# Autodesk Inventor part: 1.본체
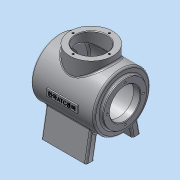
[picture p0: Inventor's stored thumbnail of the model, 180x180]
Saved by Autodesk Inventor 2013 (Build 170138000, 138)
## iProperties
Created: 2015-01
Part Number: 1.본체
Material: 알루미늄 6061
Document SubType Name: Modeling
Designer: dgall
Density: 2.71 g/cm^3
Mass: 1020.74 g
Surface Area: 1061.21 cm^2
Volume: 376.657 cm^3
Author: dgall
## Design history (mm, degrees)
sketch "스케치1"
  geometry: C1 r 50 at (0, 0); 1 further point
  constraints: 1 centre point, 1 coincident
  dimensions: "d0" = 100 diameter of C1
extrude "돌출1" new body sketch "스케치1" stored distance "d2" = 112; taper "d3" = 0 deg
sketch "스케치2"
  geometry: C1 r 38 at (0, 0); 1 further point
  constraints: 1 centre point, 1 coincident
  dimensions: "d4" = 76 diameter of C1
extrude "돌출2" join sketch "스케치2" stored distance "d6" = 122; taper "d7" = 0 deg
sketch "스케치3"
  geometry: L1 (34, -80)-(48, -80); L2 (48, -80)-(39.336, -30.865); L3 (34, -80)-(27.282, -41.901); A1 r 50 centre (0, 0) between (39.336, -30.865) and (27.282, -41.901) reference; 1 further point
  constraints: 6 end point, 2 point on circle, 1 horizontal
  dimensions: "d8" = 14 distance of L1.start L1.end; "d10" = 80 distance from line of L1 A1.centre; "d11" = 80 deg angle of L1 L3; "d12" = 100 deg angle of L1 L2; "d13" = 48 horizontal distance of L1.end point (0, 0)
extrude "돌출3" join sketch "스케치3" stored distance "d14" = 80; taper "d15" = 0 deg
node "작업 평면1"
sketch "스케치4"
  geometry: L1 (-101, 86)-(-101, 10) reference; C1 r 38 at (-39, 48); 1 further point
  constraints: 1 centre point, 1 horizontal alignment
  dimensions: "d83" = 76 diameter of C1; "d85" = 62 distance from line of L1 C1.centre
extrude "돌출4" join sketch "스케치4" stored distance "d19" = 80; taper "d20" = 0 deg
node "작업 평면3"
node "작업 평면4"
sketch "스케치14"
  geometry: C1 r 45 at (0, 0); 1 further point
  constraints: 1 centre point, 1 coincident
  dimensions: "d140" = 90 diameter of C1
extrude "돌출8" cut sketch "스케치14" distance "d142" = 97; taper "d143" = 0 deg
hole "구멍1" diameter "d27" = 54; stored, may be unused: countersink angle "d31" = 90 deg, drill point angle "d33" = 118 deg; dims "d25" = 10, "d26" = 10, "d28" = 6, "d29" = 4, "d30" = 2, "d32" = 8
sketch "스케치7"
  geometry: C1 r 27 at (0, 0) reference; 1 further point
  constraints: 1 vertical alignment
  dimensions: "d51" = 32 distance of C1.centre point (0, 32)
hole "구멍4" sketch "스케치7" at (0, 32) diameter "d52" = 3.459; stored, may be unused: countersink angle "d56" = 90 deg, drill point angle "d58" = 118 deg; dims "d53" = 8, "d54" = 4, "d55" = 2, "d57" = 10
node "작업 평면2"
sketch "스케치8"
  geometry: L1 (-26, 6)-(28, 6); L2 (28, 6)-(28, -6); L3 (28, -6)-(-26, -6); L4 (-26, -6)-(-26, 6); L5 (-61, 38)-(-61, -38) reference; 3 further points
  constraints: 8 end point, 2 midpoint, 2 parallel, 1 horizontal, 1 horizontal alignment, 1 perpendicular
  dimensions: "d65" = 54 distance of L1.start L1.end; "d67" = 12 distance of L1.end L2.end; "d80" = 62 distance from line of point (1, 6) L5
extrude "돌출6" join sketch "스케치8" stored distance "d68" = 4; taper "d69" = 0 deg
fillet "모깎기1" dims "d72" = 3
fillet "모깎기2" dims "d73" = 3
fillet "모깎기3" dims "d74" = 3
fillet "모깎기5" dims "d76" = 3
chamfer "모따기1" distance "d77" = 1; stored, may be unused: second distance "d78" = 2, angle "d79" = 45 deg
sketch "스케치10"
  geometry: L1 (28, 6)-(-26, 6) reference; L2 (28, -6)-(28, 6) reference; 5 further points
  constraints: 2 midpoint, 1 coincident, 1 horizontal alignment, 1 vertical alignment, 1 other
feature "엠보싱2" sketch "스케치10" dims "d81" = 0.5, "d82" = 0
fillet "모깎기6" dims "d106" = 3
hole "구멍9" diameter "d146" = 54; stored, may be unused: countersink angle "d150" = 90 deg, drill point angle "d152" = 118 deg; dims "d144" = 10, "d145" = 10, "d147" = 8, "d148" = 4, "d149" = 2, "d151" = 10
sketch "스케치15"
  geometry: C1 r 27 at (0, 0) reference; 3 further points
  constraints: 1 vertical alignment
  dimensions: "d153" = 32 distance of C1.centre point (0, 32)
hole "구멍10" sketch "스케치15" at (0, 32) diameter "d154" = 3.459; stored, may be unused: countersink angle "d158" = 90 deg, drill point angle "d160" = 118 deg; dims "d155" = 8, "d156" = 4, "d157" = 2, "d159" = 10
fillet "모깎기8" dims "d164" = 3
chamfer "모따기4" distance "d165" = 1; stored, may be unused: second distance "d166" = 2, angle "d167" = 45 deg
node "솔리드1"
mirror "대칭1"
pattern_circular "원형 패턴1" dims angle "d60" = 360 deg
mirror "대칭2"
pattern_circular "원형 패턴5" dims angle "d162" = 360 deg
other parameters: "d16" = -142, "d110" = -7, "d139" = -8
